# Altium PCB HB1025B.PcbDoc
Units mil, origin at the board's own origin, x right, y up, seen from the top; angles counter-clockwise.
Board outline 920.08 x 1672.05 mil, 2 copper layers (Top Layer, Bottom Layer); 30 components, 29 nets, 124 pads, 184 vias.
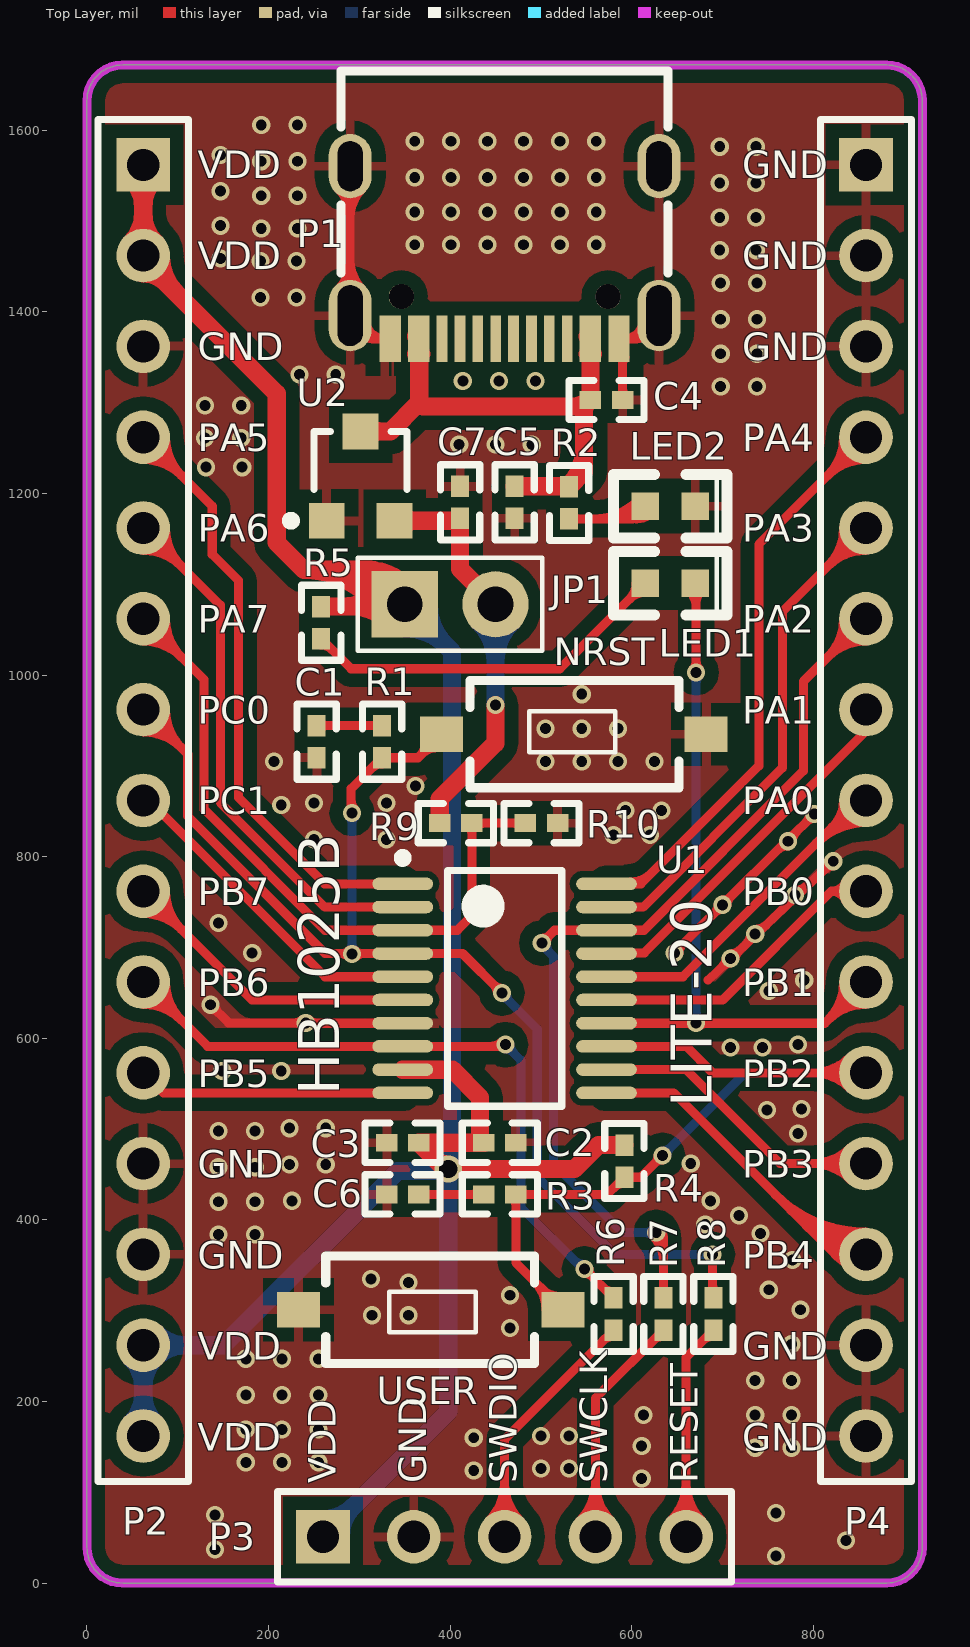
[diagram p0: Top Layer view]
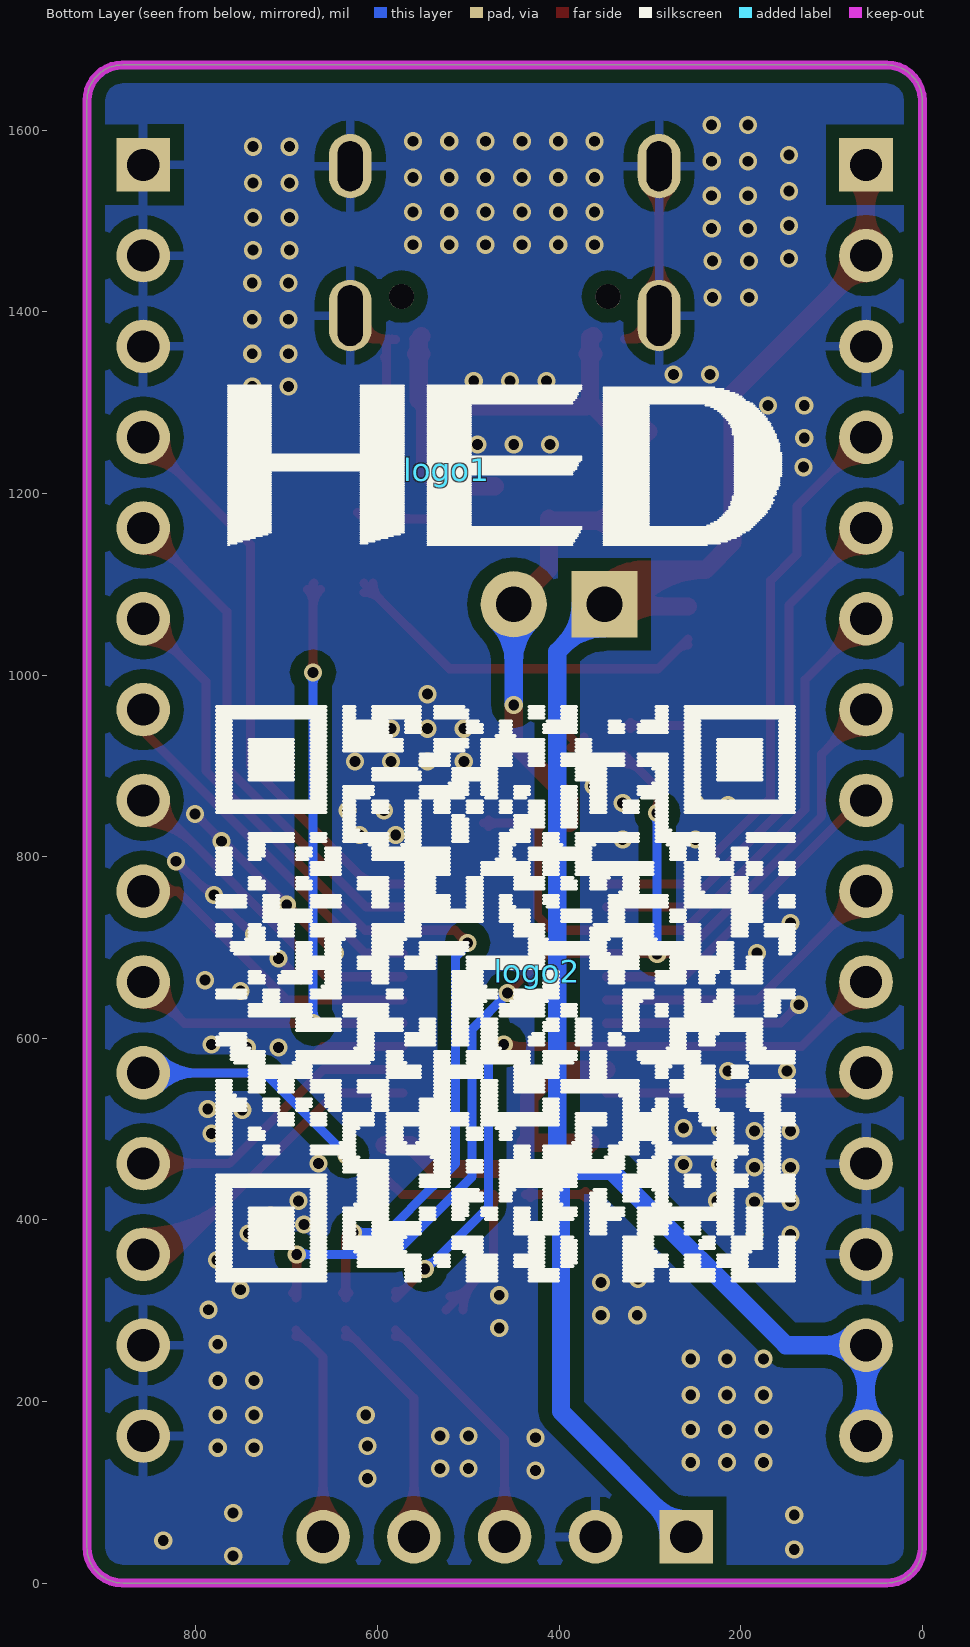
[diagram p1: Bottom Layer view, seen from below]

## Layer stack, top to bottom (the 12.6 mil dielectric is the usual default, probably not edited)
Top Layer: signal copper 1.4
Dielectric: dielectric 12.6, FR-4, Dk 4.8
Bottom Layer: signal copper 1.4

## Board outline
0,39.37 ccw(c39.37,39.37) 39.37,0 880.63,0 ccw(c880.67,39.41) 920.08,39.37 920.08,1632.68 ccw(c880.71,1632.68) 880.71,1672.05 39.37,1672.05 ccw(c39.37,1632.68) 0,1632.68

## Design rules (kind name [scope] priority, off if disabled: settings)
Clearance [(IsPad and InComponent('U1'))] p1: gap=7
Clearance Clearance_poly [(InPolygon)] p2: gap=15
Clearance Clearance_CN [(IsPad and InComponent('CN1','P1'))] p3: gap=6
Clearance Clearance_Pad [All] p4: gap=8
ComponentClearance [All] p1: gap=0 collisioncheckmode=3 verticalgap=0 showdistances=FALSE
HoleSize [All] p1: absolutevalues=TRUE maxlimit=130 minlimit=1 maxpercent=80.000 minpercent=20.000
MinimumSolderMaskSliver [All] p1: minsoldermaskwidth=0
PolygonConnect PolygonConnect_Pads [IsPad] p1: connectstyle=Relief reliefconductorwidth=10 reliefentries=4 polygonreliefangle="90 Angle"
PolygonConnect [All] p2: connectstyle=Direct reliefconductorwidth=10 reliefentries=4 polygonreliefangle="90 Angle"
RoutingVias [All] p1: holewidth=12 width=20 viastyle="Through Hole" minholewidth=10 minwidth=18 maxholewidth=300 maxwidth=500
SilkToSilkClearance [All] p1: silktosilkclearance=0
SilkscreenOverComponentPads [IsPad] p1: minsilkscreentomaskgap=0
SolderMaskExpansion [All] p1: expansion=4
TestPointUsage [All] p1: valid=0 allowmultiple=FALSE
Testpoint [All] p1: side=3 testpointundercomponent=TRUE minsize=40 maxsize=100 preferedsize=60 minholesize=0 maxholesize=40 preferedholesize=32 testpointgrid=1 style=297 order=0-112345678
Width [All] p1: maxlimit=20 minlimit=8 preferedwidth=10
19 further rules are at their usual default settings.

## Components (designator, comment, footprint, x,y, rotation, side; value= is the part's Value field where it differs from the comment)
C1 "0.1u" 0402 253,944.43 r270 top
C2 "0.1u" 0402 437,485 r0 top
C3 "0.1u" 0402 365.43,485 r180 top
C4 "0.1u" 0402 590,1303 r180 top
C5 "10u" 0402 471,1172.57 r90 top
C6 "0.1u" 0402 330,428 r0 top
C7 "10u" 0402 411,1208 r270 top
JP1 "Header 1x2" HEADER_1X2_2.54 400,1078 r0 top
LED1 "LED_G" 0603-P 615,1101.22 r0 top
LED2 "LED_R" 0603-P 615,1186.01 r0 top
logo1 "logo" LOGO 524,1226 r180 bottom
logo2 "SIGN" SIGN 424,674 r180 bottom
NRST "TS-1101-C-W" 按键_TS-1101-C-W 682,935 r180 top
P1 "TYPE-C-16P" HED-KH-TYPE-C-16P 630.08,1396 r0 top
P2 "Header 15" HDR1X15 62,1562 r270 top locked
P3 "Header 1x5" HDR1X5_2.54 260,51 r0 top
P4 "Header 15" HDR1X15 858,1562 r270 top locked
R1 "10R" 0402 325,909 r90 top
R2 "1K" 0402 531,1172 r90 top
R3 "10R" 0402 437,428 r0 top
R4 "4.7k" 0402 592,447 r90 top
R5 "510R" 0402 258,1040 r90 top
R6 "10R" 0402 580,314 r270 top
R7 "10R" 0402 635,314 r270 top
R8 "10R" 0402 690,314 r270 top
R9 "47K" 0402 424,837 r180 top
R10 "47K" 0402 483,837 r0 top
U1 "CIU32F003F5P6-TSSOP20" CIU32F003-TSSOP-20N 460,655 r0 top
U2 "ME6210A33M3G" SOT-23-3 299,1215 r0 top
USER "TS-1101-C-W" 按键_TS-1101-C-W 233,301 r0 top (schematic designator B2)

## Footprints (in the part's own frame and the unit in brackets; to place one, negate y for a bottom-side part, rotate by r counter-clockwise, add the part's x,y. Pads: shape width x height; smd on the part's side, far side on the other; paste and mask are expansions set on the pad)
0402 [mm]
  rect 0.6x0.5 smd: 1(0,0) 2(0.9,0)
  silkscreen extent -0.6,-0.55 1.5,0.55
0603-P [mil]
  rect 30x30 smd: 1(0,0) 2(55,0)
  silkscreen extent -35,-35 90,35, body extent 1,-15 60,15, height 10
CIU32F003-TSSOP-20N [mm] "TSOP, 20-Leads, Body 6.6x4.5mm (max), Pitch 0.65mm, IPC Medium Density"
  oval 1.7x0.35 smd: 1(-2.85,2.925) 2(-2.85,2.275) 3(-2.85,1.625) 4(-2.85,0.975) 5(-2.85,0.325) 6(-2.85,-0.325) 7(-2.85,-0.975) 8(-2.85,-1.625) 9(-2.85,-2.275) 10(-2.85,-2.925) 11(2.85,-2.925) 12(2.85,-2.275) 13(2.85,-1.625) 14(2.85,-0.975) 15(2.85,-0.325) 16(2.85,0.325) 17(2.85,0.975) 18(2.85,1.625) 19(2.85,2.275) 20(2.85,2.925)
  silkscreen extent -2.97,-3.3 1.6,3.77, body extent -2.25,-3.3 2.25,3.3, height 1.2
HDR1X5_2.54 [mm]
  rect 1.5x1.5 hole 0.9: 1(0,0)
  round 1.5 hole 0.9: 2(2.54,0) 3(5.08,0) 4(7.62,0) 5(10.16,0)
  silkscreen extent -1.27,-1.27 11.43,1.27
HDR1X15 [mm] "Connector; Header; 15 Position"
  rect 1.5x1.5 hole 0.9: 1(0,0)
  round 1.5 hole 0.9: 2(2.54,0) 3(5.08,0) 4(7.62,0) 5(10.16,0) 6(12.7,0) 7(15.24,0) 8(17.78,0) 9(20.32,0) 10(22.86,0) 11(25.4,0) 12(27.94,0) 13(30.48,0) 14(33.02,0) 15(35.56,0)
  silkscreen extent -1.27,-1.27 36.83,1.27
HEADER_1X2_2.54 [mm]
  rect 1.85x1.85 / inner round 1.85 / far side rect 1.85x1.85 hole 1: 1(-1.27,0)
  round 1.85 hole 1: 2(1.27,0)
  silkscreen extent -2.58,-1.3 2.58,1.3, body extent -2.67,-1.3 2.58,1.3, height 8.38
HED-KH-TYPE-C-16P [mm]
  oval 1.2x2 hole 0.7 slot 1.7 at 90 deg: 1(0,0) 2(-8.64,0)
  oval 1.2x1.8 hole 0.7 slot 1.4 at 90 deg: 3(0,4.18) 4(-8.64,4.18)
  rect 0.3x1.3 smd: A1(-0.97,-0.65) A4(-1.77,-0.65) A5(-3.07,-0.65) A6(-4.07,-0.65) A7(-4.57,-0.65) A8(-5.57,-0.65) A9(-6.87,-0.65) A12(-7.67,-0.65) B1(-7.37,-0.65) B4(-6.57,-0.65) B5(-6.07,-0.65) B6(-5.07,-0.65) B7(-3.57,-0.65) B8(-2.57,-0.65) B9(-2.07,-0.65) B12(-1.27,-0.65)
  round 0.7 hole 0.7 unplated: ""(-7.21,0.53) ""(-1.43,0.53)
  silkscreen extent -8.89,1.19 0.25,6.84
LOGO [mil]
  silkscreen extent -241,-83 369,93
SIGN [mil]
  silkscreen extent -353,-341 283,291
SOT-23-3 [mm]
  rect 1x1 smd: 1(-0.889,-1.143) 2(1.011,-1.143) 3(0.061,1.357)
  silkscreen extent -2.01,-1.27 1.36,1.36, body extent -1.39,-1.29 1.51,1.51, height 1.2
按键_TS-1101-C-W [mm] "星坤品牌"
  rect 1.2x1 smd mask+0.05: 1(0,0) 2(7.4,0)
  silkscreen extent 0.76,-1.5 6.6,1.5

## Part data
C1 C2 C3: library part Capacitor, "Capacitor, MLCC, 100nF, 16V, X7R, 10%, 0603, T=0,8mm"
C4: library part "0603 100nF 10% 50V", "贴片电容"
C5 C7: library part Capacitor, "Capacitor, MLCC, 10uF, 25V, X5R, 10%, 0805, T=0,85mm"
C6: library part Capacitor, "贴片电容"
JP1: library part MCD-00683, "Header, 2x1, 2,54mm, VR, TH, Height 5.84mm/2.54mm - Shunt Fitted by default"
LED1: library part LED1, "贴片LED 绿色"
LED2: library part LED1, "贴片LED 红色"
NRST: library part SW-PB, "Switch"
P1: library part KH-TYPE-C-16P, "TYPE-C USB接口"
P2 P4: "Header, 15-Pin"
P3: library part SWD, "Header, 1x5, 2,54mm, VR, TH, Height 5.84mm/2.54mm"
R1 R2 R3 R4 R5 R6 R7 R8 R9 R10: library part Res2, "贴片电阻"
U2: library part ME6210, "贴片LDO3.3V"
USER: library part SW-PB, "贴片按键"

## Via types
v1: diameter 20, hole 12, Top Layer to Bottom Layer, tented both sides, 183 vias
v2: diameter 30, hole 20, Top Layer to Bottom Layer, tented both sides, 1 vias

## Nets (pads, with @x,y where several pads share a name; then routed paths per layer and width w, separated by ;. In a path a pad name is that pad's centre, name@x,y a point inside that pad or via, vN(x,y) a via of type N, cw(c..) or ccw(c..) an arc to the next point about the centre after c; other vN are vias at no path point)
GND: C1.2 C2.2 C3.2 C4.1 C5.1 C6.1 C7.1 LED2.2 NRST.1 P1.1 P1.2 P1.3 P1.4 P1.A1 P1.A12 P1.B1 P1.B12 P2.3 P2.12 P2.13 P3.2 P4.1 P4.2 P4.3 P4.14 P4.15 R10.2 U1.7 U2.1 USER.1 | length 1516.1
  Top Layer w10: v1@136,632 cw(c136,619.93) 144.54,628.46 cw(c153.07,637) v1@141,637 ; v1(136,637) 156,617 v1(241,617) 241.39,616.61 U1.7 ; v1@237.46,613.46 ccw(c228.93,604.93) 228.93,617 ccw(c228.93,629.07) v1@237.46,620.54 ; v1@244.54,613.46 cw(c252.14,605.86) 252.14,616.61 ; v1@244.54,620.54 ccw(c254,630) 254,616.61 ; P1.2@276.75,1424.92 ccw(c244.96,1456.71) 289.92,1456.71 ccw(c334.88,1456.71) P1.2@303.09,1424.92 ; P1.4@276.75,1535.59 cw(c244.96,1503.8) 289.92,1503.8 cw(c334.88,1503.8) P1.4@303.09,1535.59 ; P1.4 P1.2 315.52,1370.4 P1.A12 cw(c328.11,1391.62) P1.2@307.77,1385.57 ; P1.2@298.19,1382.71 ccw(c314.7,1387.63) 314.7,1370.4 ; P1.B12@580.32,1369.53 cw(c583.51,1357.77) P1.A1@592.12,1366.39 ; C4.1@586.58,1306.42 ccw(c578.31,1314.69) 590,1314.69 ccw(c601.69,1314.69) C4.1@593.42,1306.42 ; P1.A1@588.11,1370.4 590,1368.51 C4.1 ; 590,1343.97 cw(c598.64,1343.97) P1.A1@592.53,1350.08 ; 605.3,1370.4 ccw(c605.3,1387.63) P1.1@621.81,1382.71 ; P1.1@612.23,1385.57 cw(c591.89,1391.62) P1.A1 604.48,1370.4 P1.1 ; v1(647,694) v1(700,747) v1@770,817 ; v1@647,699 ccw(c647,711.07) 655.54,702.54 ccw(c664.07,694) v1@652,694 ; 684,664 v1(822,795) ; v1@695,747 cw(c682.93,747) 691.46,738.46 cw(c700,729.93) v1@700,742 ; v1@700,752 ccw(c700,764.07) 708.54,755.54 ccw(c717.07,747) v1@705,747 ; 700.04,679.23 ccw(c691.27,688.46) v1@704,688.13 ; 700.72,679.87 cw(c708.57,671.6) v1@708.87,683 ; v1@709.13,693 ccw(c709.46,705.73) 718.23,696.49 ; v1@714,687.87 cw(c725.4,687.57) 717.55,695.85 ; 725.98,703.85 ccw(c714.88,715.55) v1@731,715.13 ; v1@736.13,720 ccw(c736.55,736.12) 747.65,724.42 ; 760.05,807.05 cw(c772,795.1) v1@772,812 ; 769.03,744.72 ccw(c755.83,758.63) v1@775,758.13 ; v1@772,822 ccw(c772,831.66) 778.83,824.83 ; v1@775,820 v1(772,817) 772,818 v1(801,847) ; v1@777,817 cw(c791.49,817) 781.24,827.24 ; v1@780.13,763 ccw(c780.63,782.17) 793.83,768.26 ; v1@796,847 cw(c783.93,847) 792.46,838.46 cw(c801,829.93) v1@801,842 ; v1@817,795.13 cw(c804.93,795.44) 813.25,786.69 cw(c821.56,777.93) v1@821.87,790
  other v1: 759,30 141,37 836,47 141,75 759,77 611,115 426,124 500,126 531,126 175,133 215,133 255,133 736,149 776,149 611,151 426,160 500,162 531,162 175,169 215,169 255,169 613,185 736,185 776,185 175,207 215,207 255,207 736,223 776,223 175,247 215,247 255,247 776,263 466,281 314,295 354,295 786,301 466,317 751,323 354,331 313,335 777,356 145,384 185,384 742,385 681,395 718,405 145,420 185,420 226,421 687,421 145,458 185,458 223,461 263,461 665,462 783,495 145,498 185,498 223,501 263,501 749,521 787,522 149,564 214,564 709,590 744,590 783,593 751,652 790,664 709,688 182,694 736,715 145,727 780,758 250,819 330,819 580,824 620,824 593,851 633,851 214,857 250,859 330,859 362,878 206,905 505,905 545,905 585,905 625,905 505,941 545,941 585,941 545,979 131,1229 171,1229 410,1254 450,1254 490,1254 130,1261 170,1261 130,1297 170,1297 698,1318 738,1318 414,1324 454,1324 494,1324 234,1331 274,1331 698,1354 738,1354 698,1392 738,1392 191,1416 231,1416 698,1432 738,1432 191,1456 231,1456 147,1459 697,1468 737,1468 361,1474 401,1474 441,1474 481,1474 521,1474 561,1474 192,1492 232,1492 147,1495 697,1504 737,1504 361,1510 401,1510 441,1510 481,1510 521,1510 561,1510 192,1528 232,1528 147,1533 697,1542 737,1542 361,1548 401,1548 441,1548 481,1548 521,1548 561,1548 192,1566 232,1566 147,1573 697,1582 737,1582 361,1588 401,1588 441,1588 481,1588 521,1588 561,1588 192,1606 232,1606
NetC1_1: C1.1 R1.2 | length 108.7
  Top Layer w10: C1.1 R1.2 ; C1.1@256.42,941.01 cw(c264.69,932.74) 264.69,944.43 cw(c264.69,956.12) C1.1@256.42,947.86 ; R1.2@321.58,941.01 ccw(c313.31,932.74) 313.31,944.43 ccw(c313.31,956.12) R1.2@321.58,947.86
NetC6_2: C6.2 R3.1 | length 108.3
  Top Layer w10: C6.2 R3.1 ; C6.2@370.83,424.58 cw(c379.09,416.31) 379.09,428 cw(c379.09,439.69) C6.2@370.83,431.42 ; R3.1@431.61,424.58 ccw(c423.34,416.31) 423.34,428 ccw(c423.34,439.69) R3.1@431.61,431.42
NetLED1_1: LED1.1 R5.1 | length 460.5
  Top Layer w10: R5.1@258,1033.19 cw(c258,1016.75) 269.63,1028.37 ; R5.1 291,1007 520.78,1007 LED1.1 ; LED1.1@605,1101.22 cw(c580.86,1101.22) 597.93,1084.15 cw(c615,1067.08) LED1.1@615,1091.22
NetLED2_1: LED2.1 R2.1 | length 220.9
  Top Layer w10: R2.1 600.99,1172 LED2.1 cw(c581.18,1219.83) 581.18,1172 ; R2.1@534.42,1168.58 cw(c542.69,1160.31) 542.69,1172 cw(c542.69,1183.69) R2.1@534.42,1175.42 ; 557.04,1172 ccw(c557.04,1243.97) LED2.1@607.93,1193.08 ; LED2.1@605.32,1172 ccw(c605.32,1195.68) LED2.1@622.07,1178.94
PA0: P4.8 U1.16 | length 501.1
  Top Layer w10: U1.16 656.27,667.8 850.47,862 P4.8 ; 803.28,814.81 cw(c858,760.09) P4.8@858,837.47 ; 820.35,831.88 cw(c858,794.23) P4.8@858,847.47 ; 821.45,832.98 ccw(c792.43,862) P4.8@833.47,862
PA1: P4.7 U1.17 | length 397.1
  Top Layer w10: U1.17 572.82,694 614,694 858,938 P4.7@858,948
PA2: P4.6 R7.1 U1.18 | length 1290.1
  Top Layer w10: v1(501,705) 514.98,718.98 U1.18 613.52,718.98 789,894.46 789,993 P4.6 ; v1@501,710 ccw(c501,722.07) 509.54,713.54 ccw(c518.07,705) v1@506,705 ; v1@623.46,382.46 cw(c595.62,354.62) 635,354.62 ; v1(627,386) 635,378 R7.1 ; v1@630.54,389.54 cw(c619.76,378.76) 635,378.76 ; R7.1@631.58,319.39 ccw(c623.31,327.66) 635,327.66 ccw(c646.69,327.66) R7.1@638.42,319.39 ; P4.6@833.47,1062 cw(c774.26,1062) 816.13,1020.13 cw(c858,978.26) P4.6@858,1037.47 ; P4.6@843.47,1062 cw(c808.4,1062) 833.2,1037.2 cw(c858,1012.4) P4.6@858,1047.47
  Bottom Layer w10: v1@501,703 514,690 514,462 538,438 ; v1@506,705 ccw(c522.9,705) 510.95,693.05 ; 538.5,437.5 538,438 ; v1@623.46,382.46 ccw(c614.93,373.93) 614.93,386 ccw(c614.93,398.07) v1@623.46,389.54 ; v1(627,386) 590,386 538,438
PA3: P4.5 U1.19 | length 707.6
  Top Layer w10: U1.19 612.57,744.57 766,898 766,1070 P4.5 ; P4.5@833.47,1162 cw(c774.26,1162) 816.13,1120.13 cw(c858,1078.26) P4.5@858,1137.47 ; P4.5@843.47,1162 cw(c808.4,1162) 833.2,1137.2 cw(c858,1112.4) P4.5@858,1147.47
PA4: P4.4 U1.20 | length 805.7
  Top Layer w10: U1.20 610.16,770.16 740,900 740,1144 P4.4 ; U1.20@598.78,772.05 ccw(c598.78,804.08) 621.43,781.43 ; P4.4@833.47,1262 cw(c774.26,1262) 816.13,1220.13 cw(c858,1178.26) P4.4@858,1237.47 ; P4.4@843.47,1262 cw(c808.4,1262) 833.2,1237.2 cw(c858,1212.4) P4.4@858,1247.47
PA5: P2.4 U1.1 | length 808.7
  Top Layer w10: P2.4@62,1237.47 cw(c62,1178.26) 103.87,1220.13 cw(c145.74,1262) P2.4@86.53,1262 ; P2.4@62,1247.47 cw(c62,1212.4) 86.8,1237.2 cw(c111.6,1262) P2.4@76.53,1262 ; P2.4 138,1186 138,1133 167,1104 167,865 261.84,770.16 U1.1
PA6: P2.5 U1.2 | length 734.2
  Top Layer w10: P2.5@62,1137.47 cw(c62,1078.26) 103.87,1120.13 cw(c145.74,1162) P2.5@86.53,1162 ; P2.5@62,1147.47 cw(c62,1112.4) 86.8,1137.2 cw(c111.6,1162) P2.5@76.53,1162 ; P2.5 147,1077 147,859.54 261.98,744.57 U1.2
PA7: P2.6 R9.1 R10.1 U1.3 | length 958.6
  Top Layer w10: P2.6@62,1037.47 cw(c62,978.26) 103.87,1020.13 cw(c145.74,1062) P2.6@86.53,1062 ; P2.6@62,1047.47 cw(c62,1012.4) 86.8,1037.2 cw(c111.6,1062) P2.6@76.53,1062 ; P2.6 129,995 129,852.09 262.09,719 U1.3 ; U1.3 407.98,718.98 424,735 R9.1 R10.1 ; R9.1@420.58,833.58 cw(c412.31,825.31) 424,825.31 cw(c435.69,825.31) R9.1@427.42,833.58 ; R9.1@429.39,833.58 cw(c437.66,825.31) 437.66,837 cw(c437.66,848.69) R9.1@429.39,840.42 ; R10.1@477.61,833.58 ccw(c469.34,825.31) 469.34,837 ccw(c469.34,848.69) R10.1@477.61,840.42
PB0: P4.9 U1.15 | length 374.8
  Top Layer w10: U1.15 700.2,642.2 820,762 ; P4.9@835.65,751.9 ccw(c820,744.83) 820,762 ; P4.9@835.65,772.1 cw(c820,779.17) 820,762 ; P4.9 820,762
PB1: LED1.2 P4.10 U1.14 | length 1070.1
  Top Layer w10: U1.14 812.61,616.61 P4.10 ; 658,616.61 ccw(c658,630) v1@667.46,620.54 ; 659.86,616.61 cw(c659.86,605.86) v1@667.46,613.46 ; LED1.2@662.93,1094.15 cw(c643.44,1074.66) 671,1074.66 ; v1@667.46,1006.54 ccw(c658.93,1015.07) 671,1015.07 ccw(c683.07,1015.07) v1@674.54,1006.54 ; LED1.2 671,1100.22 v1(671,1003) ; 671,1079.49 cw(c691.73,1079.49) LED1.2@677.07,1094.15 ; v1@674.54,613.46 cw(c682.14,605.86) 682.14,616.61 ; v1@674.54,620.54 ccw(c684,630) 684,616.61 ; P4.10@833.47,662 cw(c774.26,662) 816.13,620.13 cw(c858,578.26) P4.10@858,637.47 ; P4.10@843.47,662 cw(c808.4,662) 833.2,637.2 cw(c858,612.4) P4.10@858,647.47
  Bottom Layer w10: v1@667.46,620.54 ccw(c658.93,629.07) 671,629.07 ccw(c683.07,629.07) v1@674.54,620.54 ; v1@667.46,999.46 cw(c658.93,990.93) 671,990.93 cw(c683.07,990.93) v1@674.54,999.46 ; v1@671,616 v1(671,617) v1@671,1002
PB2: P4.11 R3.2 R4.1 U1.13 USER.2 | length 1345.2
  Top Layer w10: R3.2@469.01,424.58 cw(c460.74,416.31) 472.43,416.31 cw(c484.12,416.31) R3.2@475.86,424.58 ; R3.2@477.83,424.58 cw(c486.09,416.31) 486.09,428 cw(c486.09,439.69) R3.2@477.83,431.42 ; 492.55,332.79 cw(c460.76,301) USER.2@505.72,301 ; 502.05,323.28 ccw(c520.4,341.63) USER.2@520.4,315.68 ; USER.2 472.43,352.91 R3.2 573,428 R4.1 610,447 v1(634,471) ; U1.13 659.98,591.02 689,562 P4.11 ; 580.37,435.37 cw(c592,423.75) R4.1@592,440.19 ; R4.1@595.42,443.58 cw(c603.69,435.31) 603.69,447 cw(c603.69,458.69) R4.1@595.42,450.42 ; v1@629,471 cw(c616.93,471) 625.46,462.46 cw(c634,453.93) v1@634,466 ; P4.11@840.66,544.66 ccw(c798.79,502.79) 798.79,562 ccw(c798.79,621.21) P4.11@840.66,579.34 ; P4.11@847.73,551.73 ccw(c822.93,526.93) 822.93,562 ccw(c822.93,597.07) P4.11@847.73,572.27
  Bottom Layer w10: v1(634,471) 725,562 P4.11 ; v1@634,476 ccw(c634,488.07) 642.54,479.54 ccw(c651.07,471) v1@639,471 ; P4.11@840.66,544.66 ccw(c798.79,502.79) 798.79,562 ccw(c798.79,621.21) P4.11@840.66,579.34 ; P4.11@847.73,551.73 ccw(c822.93,526.93) 822.93,562 ccw(c822.93,597.07) P4.11@847.73,572.27
PB3: P4.12 U1.12 | length 476.7
  Top Layer w10: U1.12 660.11,565.43 763.54,462 P4.12 ; P4.12@840.66,444.66 ccw(c798.79,402.79) 798.79,462 ccw(c798.79,521.21) P4.12@840.66,479.34 ; P4.12@847.73,451.73 ccw(c822.93,426.93) 822.93,462 ccw(c822.93,497.07) P4.12@847.73,472.27
PB4: P4.13 U1.11 | length 768.8
  Top Layer w10: U1.11 646.16,539.84 824,362 ; 758.09,427.91 ccw(c858,527.83) P4.13@858,386.53 ; 775.16,410.84 ccw(c858,493.68) P4.13@858,376.53 ; 792.23,393.77 ccw(c858,459.54) P4.13@858,366.53 ; 809.3,376.7 ccw(c858,425.4) P4.13@858,356.53 ; 826.37,359.63 ccw(c858,391.26) P4.13@858,346.53 ; P4.13@834.72,354.26 ccw(c824,350.7) 824,362 ; P4.13@834.72,369.74 cw(c824,373.3) 824,362 ; P4.13@851,369 P4.13 824,362 ; P4.13@852.09,348 P4.13@858,348
PB5: P2.11 U1.10 | length 295
  Top Layer w10: P2.11 84.16,539.84 U1.10
PB6: P2.10 R6.1 U1.8 | length 986.3
  Top Layer w10: P2.10@62,637.47 cw(c62,578.26) 103.87,620.13 cw(c145.74,662) P2.10@86.53,662 ; P2.10@62,647.47 cw(c62,612.4) 86.8,637.2 cw(c111.6,662) P2.10@76.53,662 ; P2.10 132.98,591.02 U1.8 459,591 v1(461,593) ; 444.1,591 ccw(c444.1,609.9) v1@457.46,596.54 ; v1@548,341 cw(c548,328.93) 556.54,337.46 cw(c565.07,346) v1@553,346 ; v1@549,345 R6.1 ; 568.37,325.63 ccw(c580,337.25) R6.1@580,320.81
  Bottom Layer w10: v1@461,588 cw(c461,575.93) 469.54,584.46 cw(c478.07,593) v1@466,593 ; v1(461,593) 478,576 478,414 546,346 v1(548,346) v1@550,346 ; 536.05,355.95 ccw(c548,367.9) v1@548,351
PB7: P2.9 U1.6 | length 483.7
  Top Layer w10: P2.9@62,737.47 cw(c62,678.26) 103.87,720.13 cw(c145.74,762) P2.9@86.53,762 ; P2.9@62,747.47 cw(c62,712.4) 86.8,737.2 cw(c111.6,762) P2.9@76.53,762 ; P2.9 182,642 347.59,642 U1.6
PC0: NRST.2 P2.7 R1.1 R8.1 U1.4 | length 1765.6
  Top Layer w10: P2.7@62,937.47 cw(c62,878.26) 103.87,920.13 cw(c145.74,962) P2.7@86.53,962 ; P2.7@62,947.47 cw(c62,912.4) 86.8,937.2 cw(c111.6,962) P2.7@76.53,962 ; P2.7 111,913 111,844.63 262.25,693.39 U1.4 413.61,693.39 v1(457,650) ; 279,693.39 cw(c279,680) v1@288.46,689.46 ; 280.86,693.39 ccw(c280.86,704.14) v1@288.46,696.54 ; 291,862.49 ccw(c306.49,862.49) v1@295.54,851.54 ; v1(292,848) 291,849 291,875 R1.1 364.66,909 NRST.2 ; v1@295.54,689.46 cw(c305,680) 305,693.39 ; v1@295.54,696.54 ccw(c303.14,704.14) 303.14,693.39 ; 313.37,897.37 cw(c325,885.75) R1.1@325,902.19 ; R1.1@328.42,905.58 cw(c336.69,897.31) 336.69,909 cw(c336.69,920.69) R1.1@328.42,912.42 ; 366.63,910.97 ccw(c351.14,926.46) NRST.2@372.44,931.57 ; 368.38,912.72 cw(c386.72,894.37) NRST.2@386.72,920.32 ; v1@452,650 ccw(c439.93,650) 448.46,658.54 ccw(c457,667.07) v1@457,655 ; v1@685.46,358.46 cw(c676.93,349.93) 689,349.93 cw(c701.07,349.93) v1@692.54,358.46 ; 689,330.07 ccw(c704.1,330.07) R8.1@693.42,319.39 ; v1(689,362) 689,315 R8.1
  Bottom Layer w10: v1@287,693 292,698 v1(292,848) ; v1@288.46,696.54 ccw(c279.93,705.07) 292,705.07 ccw(c304.07,705.07) v1@295.54,696.54 ; v1@288.46,844.46 cw(c279.93,835.93) 292,835.93 cw(c304.07,835.93) v1@295.54,844.46 ; v1@457,645 cw(c457,635.34) 463.83,642.17 ; v1@457,649 496,610 496,447.47 581.47,362 v1(689,362) ; v1@462,650 ccw(c476.49,650) 466.24,639.76 ; v1@685.46,358.46 ccw(c676.93,349.93) 676.93,362 ccw(c676.93,374.07) v1@685.46,365.54
  other v1: 292,693
PC1: P2.8 U1.5 | length 366.2
  Top Layer w10: P2.8 68.18,862 262.38,667.8 U1.5
RESET: P3.5 R8.2 | length 401
  Top Layer w10: P3.5@642.66,68.34 ccw(c600.79,110.21) 660,110.21 ccw(c719.21,110.21) P3.5@677.34,68.34 ; P3.5@649.73,61.27 ccw(c624.93,86.07) 660,86.07 ccw(c695.07,86.07) P3.5@670.27,61.27 ; P3.5 660,248.57 R8.2 ; 678.37,266.94 cw(c690,255.31) R8.2@690,271.76
SWCLK: P3.4 R7.2 | length 419.7
  Top Layer w10: P3.4@542.66,68.34 ccw(c500.79,110.21) 560,110.21 ccw(c619.21,110.21) P3.4@577.34,68.34 ; P3.4@549.73,61.27 ccw(c524.93,86.07) 560,86.07 ccw(c595.07,86.07) P3.4@570.27,61.27 ; P3.4 560,203.57 R7.2 ; 623.37,266.94 cw(c635,255.31) R7.2@635,271.76
SWDIO: P3.3 R6.2 | length 438.3
  Top Layer w10: P3.3@442.66,68.34 ccw(c400.79,110.21) 460,110.21 ccw(c519.21,110.21) P3.3@477.34,68.34 ; P3.3@449.73,61.27 ccw(c424.93,86.07) 460,86.07 ccw(c495.07,86.07) P3.3@470.27,61.27 ; P3.3 460,158.57 R6.2 ; 568.37,266.94 cw(c580,255.31) R6.2@580,271.76
VBUS_5V: C4.2 C5.2 P1.A4 P1.A9 P1.B4 P1.B9 R2.2 U2.3 | length 740.2
  Top Layer w10: R2.2@530.43,1208 R2.2 ; P1.A4@554.57,1364.58 P1.A4
  Top Layer w20: U2.3 334.43,1268.43 366,1300 ; U2.3@308.25,1261.58 cw(c324.78,1245.04) 324.78,1268.43 cw(c324.78,1291.81) U2.3@308.25,1275.27 ; P1.A9@362.5,1353.62 cw(c354.03,1345.16) P1.B4@366,1345.16 ; P1.B4@366,1347.52 cw(c374.62,1347.52) P1.B4@368.52,1353.62 ; P1.B4@366,1371.99 366,1370.41 366,1300 ; C5.2 R2.2@530.43,1208 ; R2.2 547.57,1224 C4.2@547.57,1296 ; R2.2@531.11,1209.29 ccw(c491.38,1249.02) 547.57,1249.02 ; 536.08,1296 ccw(c536.08,1319.52) C4.2@552.71,1302.89 ; 547.57,1291.23 cw(c564.37,1291.23) C4.2@552.49,1303.11 ; P1.B9@551.48,1353.61 cw(c544.01,1346.15) P1.A4@554.57,1346.15 ; P1.B9@551.48,1373.3 cw(c544.01,1365.83) P1.A4@554.57,1365.83 ; P1.A4@554.57,1346.54 cw(c564.56,1346.54) P1.A4@557.49,1353.61 ; P1.A4@554.57,1364.58 C4.2 C4.2@547.57,1296 ; 366,1300 370,1296 C4.2@547.57,1296 ; P1.A9@362.5,1373.3 cw(c354.03,1364.84) 366,1364.84 ccw(c354.03,1364.84) P1.A9@362.5,1373.3
VDD: C2.1 C3.1 JP1.1 P2.1 P2.2 P2.14 P2.15 P3.1 R4.2 R5.2 U1.9 | length 3851.2
  Top Layer w20: P2.2@48.19,1475.81 ccw(c14.86,1509.14) 62,1509.14 ccw(c109.14,1509.14) P2.2@75.81,1475.81 ; P2.1@48.19,1548.19 cw(c14.86,1514.86) 62,1514.86 cw(c109.14,1514.86) P2.1@75.81,1548.19 ; P2.2@62,1442.47 cw(c62,1407.27) 86.89,1432.16 ; P2.1 P2.2 62,1457.06 209,1310.06 209,1146 239,1116 ; P2.2@81.53,1462 ccw(c140.61,1462) 98.83,1420.22 ; R5.2 347.43,1075.43 JP1.1 312,1116 239,1116 ; 273.47,1116 cw(c273.47,1034.27) JP1.1@344.43,1074.82 ; 280.03,1075.43 ccw(c280.03,1147.97) JP1.1@331.32,1096.68 ; 292.42,1075.43 cw(c292.42,1020.42) JP1.1@331.32,1059.32 ; 307.93,1116 cw(c307.93,1053.96) JP1.1@361.79,1084.74 ; JP1.1@327.06,1064.89 ccw(c239,1014.58) 239,1116 ; U1.9 402.43,565.43 433,534.87 433,489 C2.1 C3.1 v2@393.43,457 ; 383.38,467.06 ccw(c398,481.68) v2@398,461 ; v2(398,456) 537,456 563.43,482.43 R4.2 R4.2@591.57,482.43
  Bottom Layer w20: P2.15@48.19,175.81 ccw(c14.86,209.14) 62,209.14 ccw(c109.14,209.14) P2.15@75.81,175.81 ; P2.14@48.19,248.19 cw(c14.86,214.86) 62,214.86 cw(c109.14,214.86) 75.81,248.19 cw(c109.14,214.86) 109.14,262 cw(c109.14,309.14) P2.14@75.81,275.81 ; P2.15 P2.14 150.4,262 342.4,454 398,454 398,189 P3.1 ; P3.1@260,70.53 ccw(c260,117.67) 293.34,84.34 ccw(c326.67,51) P3.1@279.53,51 ; JP1.1@350,1051.58 cw(c350,987.81) 395.1,1032.9 cw(c440.19,1078) JP1.1@376.42,1078 ; JP1.1 402,1026 v2@402,457 ; 381.1,454 ccw(c381.1,472.9) 394.46,459.54 ccw(c376.27,477.73) 402,477.73
VLDO: C7.2 JP1.2 R9.2 U2.2 | length 586.3
  Top Layer w20: U2.2 408.43,1170 C7.2 411,1117 JP1.2 ; U2.2@345.65,1163.15 cw(c362.18,1146.62) 362.18,1170 cw(c362.18,1193.38) U2.2@345.65,1176.85 ; R9.2 388.57,863.57 450,925 v1(450,967)
  Bottom Layer w20: JP1.2@431.32,1059.32 cw(c386.22,1014.22) 450,1014.22 cw(c513.78,1014.22) JP1.2@468.68,1059.32 ; v1@450,968 JP1.2
pads on no net: P1. P1.A5 P1.A6 P1.A7 P1.A8 P1.B5 P1.B6 P1.B7 P1.B8

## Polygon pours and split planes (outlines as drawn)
GND on Top Layer "Top Layer-No Net" (solid, remove dead copper, pour order 1000): -2.77,1696.23 918.23,1696.23 918.23,-0.77 -0.77,-0.77 -0.77,1694.21 -2.77,1696.23
GND on Bottom Layer "Bottom Layer-GND" (solid, remove dead copper, pour order 1001): 0,0 0,1672 920.08,1672 920.08,0

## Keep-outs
Keep-Out Layer:
  the board outline again, w10

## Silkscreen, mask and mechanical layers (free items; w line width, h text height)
Top Overlay:
  text "VDD" at 122,1547 h30
  text "GND" at 722,1547 h30
  text "VDD" at 122,1446.93 h30
  text "GND" at 722,1446.93 h30
  text "GND" at 122,1346.86 h30
  text "GND" at 722,1346.86 h30
  text "PA5" at 122,1246.79 h30
  text "PA4" at 722,1246.79 h30
  text "PA6" at 122,1146.71 h30
  text "PA3" at 722,1146.71 h30
  text "PA7" at 122,1046.64 h30
  text "PA2" at 722,1046.64 h30
  text "PC0" at 122,946.57 h30
  text "PA1" at 722,946.57 h30
  text "PC1" at 122,846.5 h30
  text "PA0" at 722,846.5 h30
  text "PB7" at 122,746.43 h30
  text "PB0" at 722,746.43 h30
  text "PB6" at 122,646.36 h30
  text "PB1" at 722,646.36 h30
  text "PB5" at 122,546.29 h30
  text "PB2" at 722,546.29 h30
  text "HB1025B" at 278,537 h45 r90
  text "LITE-20" at 688,524 h45 r90
  text "GND" at 122,446.21 h30
  text "PB3" at 722,446.21 h30
  text "GND" at 122,346.14 h30
  text "PB4" at 722,346.14 h30
  text "VDD" at 122,246.07 h30
  text "GND" at 722,246.07 h30
  text "VDD" at 122,146 h30
  text "GND" at 722,146 h30
  text "VDD" at 274,110 h30 r90
  text "GND" at 373.75,110 h30 r90
  text "SWDIO" at 473.5,110 h30 r90
  text "SWCLK" at 573.25,110 h30 r90
  text "RESET" at 673,110 h30 r90
Mechanical 1:
  the board outline again, w10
